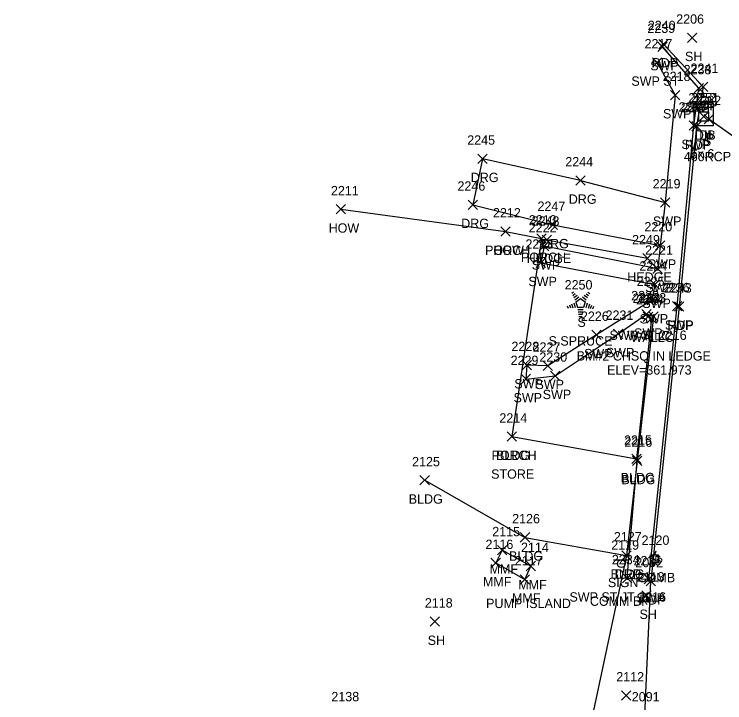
# Model space of a CAD drawing. Extents: x 462930 to 463548, y 29607 to 30453.
# Drawn here: x 463351.85 to 463398.16, y 30246.27 to 30291.16 of the extents above; entities that cross this region are included whole.
import ezdxf

# ---------------------------------------------------------------- set-up
doc = ezdxf.new("R2010")
doc.units = 0
for name, color, linetype in [('D_A', 7, 'Continuous'), ('D_C', 7, 'Continuous'), ('D_I', 7, 'Continuous'), ('D_TIC', 7, 'Continuous'), ('DCP', 7, 'Continuous'), ('DS', 7, 'Continuous'), ('L_A', 7, 'Continuous'), ('L_C', 7, 'Continuous'), ('L_I', 7, 'Continuous'), ('L_TIC', 7, 'Continuous'), ('LAHR', 7, 'Continuous'), ('LBC', 7, 'Continuous'), ('LBF', 7, 'Continuous'), ('LDEFAULT', 7, 'Continuous'), ('LTC', 7, 'Continuous'), ('LW', 7, 'Continuous'), ('P_A', 7, 'Continuous'), ('P_I', 7, 'Continuous'), ('P_TIC', 7, 'Continuous'), ('PET', 7, 'Continuous'), ('R_A', 7, 'Continuous'), ('R_I', 7, 'Continuous'), ('R_TIC', 7, 'Continuous'), ('RDG', 7, 'Continuous'), ('RDP', 7, 'Continuous'), ('RSW', 7, 'Continuous'), ('S_A', 7, 'Continuous'), ('S_C', 7, 'Continuous'), ('S_I', 7, 'Continuous'), ('SSGN', 7, 'Continuous'), ('U_A', 7, 'Continuous'), ('U_I', 7, 'Continuous'), ('UP', 7, 'Continuous')]:
    doc.layers.add(name, color=color, linetype=linetype)

msp = doc.modelspace()

# ---------------------------------------------------------------- linework, layer by layer
at = {"layer": 'D_TIC'}
for points in [[(463396.479, 30284.195), (463397.089, 30284.805)], [(463397.089, 30284.195), (463396.479, 30284.805)], [(463396.809, 30284.016), (463397.419, 30284.626)], [(463397.419, 30284.016), (463396.809, 30284.626)]]:
    msp.add_lwpolyline(points, dxfattribs=at)
at = {"layer": 'DCP'}
msp.add_lwpolyline([(463406.672, 30277.555), (463397.114, 30284.321)], dxfattribs=at)
at = {"layer": 'DS'}
for p, q in [((463396.173, 30285.108), (463397.392, 30285.108)), ((463396.173, 30283.889), (463396.173, 30285.108)), ((463397.392, 30285.108), (463397.392, 30283.889)), ((463396.478, 30284.194), (463396.478, 30284.803)), ((463396.478, 30284.803), (463397.087, 30284.803)), ((463396.784, 30284.499), (463396.784, 30284.499)), ((463396.784, 30284.499), (463396.784, 30284.499)), ((463397.087, 30284.803), (463397.087, 30284.194)), ((463397.087, 30284.194), (463396.478, 30284.194)), ((463397.392, 30283.889), (463396.173, 30283.889))]:
    msp.add_line(p, q, dxfattribs=at)
at = {"layer": 'L_TIC'}
for points in [[(463395.721, 30289.323), (463396.331, 30289.933)], [(463396.331, 30289.323), (463395.721, 30289.933)], [(463372.834, 30278.135), (463373.444, 30278.745)], [(463373.444, 30278.135), (463372.834, 30278.745)], [(463383.565, 30276.688), (463384.175, 30277.298)], [(463384.175, 30276.688), (463383.565, 30277.298)], [(463383.565, 30276.688), (463384.175, 30277.298)], [(463384.175, 30276.688), (463383.565, 30277.298)], [(463385.902, 30276.227), (463386.512, 30276.837)], [(463386.512, 30276.227), (463385.902, 30276.837)], [(463386.258, 30276.152), (463386.868, 30276.762)], [(463386.868, 30276.152), (463386.258, 30276.762)], [(463392.808, 30274.939), (463393.418, 30275.549)], [(463393.418, 30274.939), (463392.808, 30275.549)], [(463392.85, 30271.115), (463393.46, 30271.725)], [(463393.46, 30271.115), (463392.85, 30271.725)], [(463393.079, 30271.016), (463393.689, 30271.626)], [(463393.689, 30271.016), (463393.079, 30271.626)], [(463383.985, 30263.314), (463384.595, 30263.924)], [(463384.595, 30263.314), (463383.985, 30263.924)], [(463383.985, 30263.314), (463384.595, 30263.924)], [(463384.595, 30263.314), (463383.985, 30263.924)], [(463392.107, 30261.866), (463392.717, 30262.476)], [(463392.717, 30261.866), (463392.107, 30262.476)], [(463392.153, 30261.737), (463392.763, 30262.347)], [(463392.763, 30261.737), (463392.153, 30262.347)], [(463378.295, 30260.466), (463378.905, 30261.076)], [(463378.905, 30260.466), (463378.295, 30261.076)], [(463384.833, 30256.748), (463385.443, 30257.358)], [(463385.443, 30256.748), (463384.833, 30257.358)], [(463383.348, 30255.906), (463383.958, 30256.516)], [(463383.958, 30255.906), (463383.348, 30256.516)], [(463391.445, 30255.571), (463392.055, 30256.181)], [(463392.055, 30255.571), (463391.445, 30256.181)], [(463382.922, 30255.075), (463383.532, 30255.685)], [(463383.532, 30255.075), (463382.922, 30255.685)], [(463385.221, 30254.879), (463385.831, 30255.489)], [(463385.831, 30254.879), (463385.221, 30255.489)], [(463384.814, 30254.004), (463385.424, 30254.614)], [(463385.424, 30254.004), (463384.814, 30254.614)], [(463392.758, 30252.952), (463393.368, 30253.562)], [(463393.368, 30252.952), (463392.758, 30253.562)], [(463378.954, 30251.255), (463379.564, 30251.865)], [(463379.564, 30251.255), (463378.954, 30251.865)], [(463391.428, 30246.438), (463392.038, 30247.048)], [(463392.038, 30246.438), (463391.428, 30247.048)]]:
    msp.add_lwpolyline(points, dxfattribs=at)
at = {"layer": 'LAHR'}
msp.add_lwpolyline([(463386.563, 30276.457), (463393.113, 30275.244)], dxfattribs=at)
at = {"layer": 'LBC'}
for points in [[(463373.139, 30278.44), (463383.87, 30276.993)], [(463384.29, 30263.619), (463392.412, 30262.171), (463392.458, 30262.042)], [(463392.458, 30262.042), (463391.75, 30255.876)], [(463378.6, 30260.771), (463385.138, 30257.053), (463391.75, 30255.876)]]:
    msp.add_lwpolyline(points, dxfattribs=at)
at = {"layer": 'LBF'}
msp.add_lwpolyline([(463383.87, 30276.993), (463386.207, 30276.532), (463384.29, 30263.619)], dxfattribs=at)
at = {"layer": 'LDEFAULT'}
for points in [[(463385.526, 30255.184), (463383.653, 30256.211), (463383.227, 30255.38), (463385.119, 30254.309)], [(463385.119, 30254.309), (463385.526, 30255.184)]]:
    msp.add_lwpolyline(points, dxfattribs=at)
at = {"layer": 'LTC'}
for p, q in [((463388.192, 30272.972), (463388.3, 30273.051)), ((463388.256, 30272.83), (463388.417, 30272.947)), ((463388.32, 30272.688), (463388.534, 30272.844)), ((463389.002, 30272.833), (463389.209, 30272.682)), ((463389.115, 30272.939), (463389.282, 30272.817)), ((463389.228, 30273.045), (463389.355, 30272.952)), ((463388.384, 30272.546), (463388.651, 30272.741)), ((463388.452, 30272.408), (463388.76, 30272.631)), ((463388.452, 30272.408), (463388.57, 30272.044)), ((463388.76, 30272.631), (463389.064, 30272.41)), ((463388.888, 30272.727), (463389.135, 30272.547)), ((463389.064, 30272.41), (463388.945, 30272.044)), ((463387.897, 30272.143), (463387.943, 30272)), ((463388.036, 30272.209), (463388.1, 30272.01)), ((463388.175, 30272.275), (463388.257, 30272.02)), ((463388.313, 30272.341), (463388.414, 30272.03)), ((463388.945, 30272.044), (463388.57, 30272.044)), ((463388.933, 30271.891), (463388.584, 30271.891)), ((463389.198, 30272.328), (463389.095, 30272.011)), ((463389.333, 30272.252), (463389.245, 30271.982)), ((463389.469, 30272.175), (463389.396, 30271.953)), ((463389.604, 30272.099), (463389.547, 30271.924)), ((463388.908, 30271.739), (463388.607, 30271.739)), ((463388.882, 30271.587), (463388.629, 30271.587)), ((463388.857, 30271.434), (463388.651, 30271.434))]:
    msp.add_line(p, q, dxfattribs=at)
at = {"layer": 'LW'}
for points in [[(463393.384, 30271.321), (463392.412, 30262.171)], [(463393.155, 30271.42), (463393.384, 30271.321)]]:
    msp.add_lwpolyline(points, dxfattribs=at)
at = {"layer": 'P_TIC'}
for points in [[(463393.855, 30288.906), (463394.465, 30289.516)], [(463394.465, 30288.906), (463393.855, 30289.516)], [(463396.441, 30286.118), (463397.051, 30286.728)], [(463397.051, 30286.118), (463396.441, 30286.728)], [(463396.017, 30283.551), (463396.627, 30284.161)], [(463396.627, 30283.551), (463396.017, 30284.161)], [(463394.878, 30271.79), (463395.488, 30272.4)], [(463395.488, 30271.79), (463394.878, 30272.4)], [(463393.041, 30253.888), (463393.651, 30254.498)], [(463393.651, 30253.888), (463393.041, 30254.498)]]:
    msp.add_lwpolyline(points, dxfattribs=at)
at = {"layer": 'PET'}
for points in [[(463394.16, 30289.211), (463396.746, 30286.423), (463396.322, 30283.856), (463395.183, 30272.095)], [(463395.183, 30272.095), (463393.346, 30254.193)], [(463351.849, 30230.001), (463360.302, 30224.79), (463363.81, 30222.829), (463366.719, 30221.627), (463371.212, 30221.775), (463377.641, 30225.283), (463383.918, 30231.013), (463388.099, 30237.45), (463392.941, 30245.442), (463393.346, 30254.193)]]:
    msp.add_lwpolyline(points, dxfattribs=at)
at = {"layer": 'R_TIC'}
for points in [[(463393.804, 30288.722), (463394.414, 30289.332)], [(463394.414, 30288.722), (463393.804, 30289.332)], [(463393.444, 30287.714), (463394.054, 30288.324)], [(463394.054, 30287.714), (463393.444, 30288.324)], [(463396.163, 30286.025), (463396.773, 30286.635)], [(463396.773, 30286.025), (463396.163, 30286.635)], [(463394.629, 30285.586), (463395.239, 30286.196)], [(463395.239, 30285.586), (463394.629, 30286.196)], [(463395.832, 30283.591), (463396.442, 30284.201)], [(463396.442, 30283.591), (463395.832, 30284.201)], [(463382.063, 30281.434), (463382.673, 30282.044)], [(463382.673, 30281.434), (463382.063, 30282.044)], [(463388.452, 30280.018), (463389.062, 30280.628)], [(463389.062, 30280.018), (463388.452, 30280.628)], [(463381.442, 30278.436), (463382.052, 30279.046)], [(463382.052, 30278.436), (463381.442, 30279.046)], [(463393.976, 30278.583), (463394.586, 30279.193)], [(463394.586, 30278.583), (463393.976, 30279.193)], [(463386.643, 30277.118), (463387.253, 30277.728)], [(463387.253, 30277.118), (463386.643, 30277.728)], [(463386.072, 30275.73), (463386.682, 30276.34)], [(463386.682, 30275.73), (463386.072, 30276.34)], [(463393.634, 30275.784), (463394.244, 30276.394)], [(463394.244, 30275.784), (463393.634, 30276.394)], [(463385.857, 30274.65), (463386.467, 30275.26)], [(463386.467, 30274.65), (463385.857, 30275.26)], [(463393.48, 30274.261), (463394.09, 30274.871)], [(463394.09, 30274.261), (463393.48, 30274.871)], [(463393.285, 30273.228), (463393.895, 30273.838)], [(463393.895, 30273.228), (463393.285, 30273.838)], [(463393.105, 30272.218), (463393.715, 30272.828)], [(463393.715, 30272.218), (463393.105, 30272.828)], [(463394.756, 30271.816), (463395.366, 30272.426)], [(463395.366, 30271.816), (463394.756, 30272.426)], [(463392.748, 30271.289), (463393.358, 30271.899)], [(463393.358, 30271.289), (463392.748, 30271.899)], [(463393.211, 30271.147), (463393.821, 30271.757)], [(463393.821, 30271.147), (463393.211, 30271.757)], [(463389.488, 30269.946), (463390.098, 30270.556)], [(463390.098, 30269.946), (463389.488, 30270.556)], [(463390.904, 30270.015), (463391.514, 30270.625)], [(463391.514, 30270.015), (463390.904, 30270.625)], [(463384.943, 30267.978), (463385.553, 30268.588)], [(463385.553, 30267.978), (463384.943, 30268.588)], [(463386.319, 30267.938), (463386.929, 30268.548)], [(463386.929, 30267.938), (463386.319, 30268.548)], [(463386.79, 30267.286), (463387.4, 30267.896)], [(463387.4, 30267.286), (463386.79, 30267.896)], [(463384.891, 30267.071), (463385.501, 30267.681)], [(463385.501, 30267.071), (463384.891, 30267.681)], [(463391.445, 30255.571), (463392.055, 30256.181)], [(463392.055, 30255.571), (463391.445, 30256.181)], [(463391.487, 30254.08), (463392.097, 30254.69)], [(463392.097, 30254.08), (463391.487, 30254.69)], [(463392.903, 30254.011), (463393.513, 30254.621)], [(463393.513, 30254.011), (463392.903, 30254.621)]]:
    msp.add_lwpolyline(points, dxfattribs=at)
at = {"layer": 'RDG'}
for points in [[(463388.757, 30280.323), (463382.368, 30281.739), (463381.747, 30278.741), (463386.948, 30277.423)], [(463388.757, 30280.323), (463394.281, 30278.888)], [(463386.948, 30277.423), (463393.939, 30276.089)]]:
    msp.add_lwpolyline(points, dxfattribs=at)
at = {"layer": 'RDP'}
msp.add_lwpolyline([(463391.75, 30255.876), (463387.853, 30237.498), (463385.416, 30235.81), (463378.004, 30240.013), (463371.934, 30243.569)], dxfattribs=at)
at = {"layer": 'RSW'}
for points in [[(463391.792, 30254.385), (463393.208, 30254.316), (463395.061, 30272.121), (463396.137, 30283.896), (463396.468, 30286.33), (463394.109, 30289.027)], [(463393.749, 30288.019), (463394.934, 30285.891), (463394.281, 30278.888), (463393.939, 30276.089), (463393.785, 30274.566), (463386.377, 30276.035), (463386.162, 30274.955), (463393.59, 30273.533), (463393.41, 30272.523), (463389.793, 30270.251), (463386.624, 30268.243), (463385.248, 30268.283), (463385.196, 30267.376), (463387.095, 30267.591), (463391.209, 30270.32), (463393.053, 30271.594), (463393.516, 30271.452)], [(463393.516, 30271.452), (463392.458, 30262.042)], [(463391.792, 30254.385), (463392.458, 30262.042)]]:
    msp.add_lwpolyline(points, dxfattribs=at)
at = {"layer": 'SSGN'}
for p, q in [((463390.913, 30255.59), (463391.929, 30255.59)), ((463391.415, 30255.336), (463391.415, 30255.336))]:
    msp.add_line(p, q, dxfattribs=at)
msp.add_circle((463391.415, 30255.336), 0.254, dxfattribs=at)
at = {"layer": 'UP'}
for p, q in [((463393.658, 30256.157), (463393.582, 30255.903)), ((463393.328, 30255.395), (463393.328, 30255.903)), ((463393.328, 30255.903), (463393.836, 30255.903)), ((463393.836, 30255.903), (463393.836, 30255.395)), ((463393.836, 30255.395), (463393.328, 30255.395)), ((463393.506, 30255.141), (463393.582, 30255.395)), ((463393.582, 30255.649), (463393.582, 30255.649))]:
    msp.add_line(p, q, dxfattribs=at)
msp.add_circle((463393.582, 30255.649), 0.254, dxfattribs=at)

# ---------------------------------------------------------------- texts
at = {"layer": 'D_A'}
for s, height, p in [('DIB', 0.6096, (463396.206, 30282.976)), ('DI', 0.6096, (463396.496, 30282.975)), ('P', 0.61, (463396.924, 30282.797))]:
    msp.add_text(s, height=height, dxfattribs=at).set_placement(p)
at = {"layer": 'D_C'}
for s, p in [('460RCP', (463395.489, 30281.578)), ('.6x.6', (463395.706, 30281.756))]:
    msp.add_text(s, height=0.6096, dxfattribs=at).set_placement(p)
at = {"layer": 'D_I'}
for s, p in [('2252', (463395.79, 30285.414)), ('2251', (463395.963, 30285.413)), ('2262', (463396.106, 30285.235))]:
    msp.add_text(s, height=0.6096, dxfattribs=at).set_placement(p)
at = {"layer": 'L_A'}
for s, height, p in [('SH', 0.6096, (463395.565, 30288.104)), ('HOW', 0.6096, (463372.342, 30276.916)), ('PORCH', 0.6096, (463382.536, 30275.469)), ('HOW', 0.6096, (463383.073, 30275.469)), ('PORCH', 0.6096, (463384.873, 30275.008)), ('HEDGE', 0.6096, (463385.253, 30274.933)), ('HEDGE', 0.6096, (463391.803, 30273.72)), ('S', 0.61, (463388.555, 30270.775)), ('WALLC', 0.6096, (463391.794, 30269.896)), ('WALLC', 0.6096, (463392.023, 30269.797)), ('PORCH', 0.6096, (463382.956, 30262.095)), ('BLDG', 0.6096, (463383.251, 30262.095)), ('BLDG', 0.6096, (463391.373, 30260.647)), ('BLDG', 0.6096, (463391.419, 30260.518)), ('BLDG', 0.6096, (463377.561, 30259.247)), ('BLDG', 0.6096, (463384.099, 30255.529)), ('MMF', 0.6096, (463382.825, 30254.687)), ('BLDG', 0.6096, (463390.711, 30254.352)), ('MMF', 0.6096, (463382.399, 30253.856)), ('MMF', 0.6096, (463384.698, 30253.66)), ('MMF', 0.6096, (463384.291, 30252.785)), ('SH', 0.6096, (463392.602, 30251.733)), ('SH', 0.6096, (463378.798, 30250.036))]:
    msp.add_text(s, height=height, dxfattribs=at).set_placement(p)
at = {"layer": 'L_C'}
for s, p in [('S.SPRUCE', (463386.673, 30269.556)), ('BM#2 CHSQ IN LEDGE', (463388.507, 30268.578)), ('ELEV=361.973', (463390.485, 30267.663)), ('STORE', (463382.932, 30260.876)), ('PUMP ISLAND', (463382.605, 30252.441))]:
    msp.add_text(s, height=0.6096, dxfattribs=at).set_placement(p)
at = {"layer": 'L_I'}
for s, p in [('2206', (463394.992, 30290.542)), ('2211', (463372.491, 30279.354)), ('2212', (463383.049, 30277.907)), ('2212', (463383.049, 30277.907)), ('2213', (463385.386, 30277.446)), ('2248', (463385.569, 30277.371)), ('2249', (463392.117, 30276.158)), ('2250', (463387.722, 30273.213)), ('2263', (463392.147, 30272.334)), ('2264', (463392.376, 30272.235)), ('2214', (463383.469, 30264.533)), ('2214', (463383.469, 30264.533)), ('2215', (463391.591, 30263.085)), ('2216', (463391.62, 30262.956)), ('2125', (463377.779, 30261.685)), ('2126', (463384.3, 30257.967)), ('2115', (463383.005, 30257.125)), ('2127', (463390.929, 30256.79)), ('2116', (463382.562, 30256.294)), ('2114', (463384.878, 30256.098)), ('2117', (463384.471, 30255.223)), ('2113', (463392.415, 30254.171)), ('2118', (463378.611, 30252.474)), ('2112', (463391.085, 30247.657)), ('2138', (463372.518, 30246.364))]:
    msp.add_text(s, height=0.6096, dxfattribs=at).set_placement(p)
at = {"layer": 'LTC'}
msp.add_text('.', height=0.316, rotation=270, dxfattribs=at).set_placement((463388.725, 30272.331))
at = {"layer": 'P_A'}
for p in [(463393.394, 30287.687), (463395.98, 30284.899), (463395.556, 30282.332), (463394.417, 30270.571), (463392.58, 30252.669)]:
    msp.add_text('RDP', height=0.6096, dxfattribs=at).set_placement(p)
at = {"layer": 'P_I'}
for s, p in [('2240', (463393.14, 30290.125)), ('2241', (463395.925, 30287.337)), ('2242', (463395.328, 30284.77)), ('2243', (463394.189, 30273.009)), ('2092', (463392.328, 30255.107)), ('2091', (463392.096, 30246.356))]:
    msp.add_text(s, height=0.6096, dxfattribs=at).set_placement(p)
at = {"layer": 'R_A'}
for s, p in [('SWP', (463393.305, 30287.503)), ('SWP ST', (463392.071, 30286.495)), ('SWP', (463395.664, 30284.806)), ('SWP', (463394.13, 30284.367)), ('SWP', (463395.333, 30282.372)), ('DRG', (463381.602, 30280.215)), ('DRG', (463387.991, 30278.799)), ('SWP', (463393.477, 30277.364)), ('DRG', (463380.981, 30277.217)), ('DRG', (463386.182, 30275.899)), ('SWP', (463393.135, 30274.565)), ('SWP', (463385.573, 30274.511)), ('SWP', (463385.358, 30273.431)), ('SWP', (463392.981, 30273.042)), ('SWP', (463392.786, 30272.009)), ('SWP', (463392.606, 30270.999)), ('SWP', (463394.257, 30270.597)), ('SWP JT 2216', (463390.643, 30269.928)), ('SWP', (463392.249, 30270.07)), ('SWP', (463388.989, 30268.727)), ('SWP', (463390.405, 30268.796)), ('SWP', (463384.444, 30266.759)), ('SWP', (463385.82, 30266.719)), ('SWP', (463384.392, 30265.852)), ('SWP', (463386.291, 30266.067)), ('DRP', (463390.984, 30254.352)), ('SWP ST JT 2216', (463388.036, 30252.861)), ('SWP', (463392.404, 30252.792))]:
    msp.add_text(s, height=0.6096, dxfattribs=at).set_placement(p)
at = {"layer": 'R_I'}
for s, p in [('2239', (463393.113, 30289.941)), ('2217', (463392.928, 30288.933)), ('2238', (463395.474, 30287.244)), ('2218', (463394.113, 30286.805)), ('2237', (463395.143, 30284.81)), ('2245', (463381.374, 30282.653)), ('2244', (463387.763, 30281.237)), ('2246', (463380.737, 30279.655)), ('2219', (463393.458, 30279.802)), ('2247', (463385.954, 30278.337)), ('2222', (463385.383, 30276.949)), ('2220', (463392.919, 30277.003)), ('2223', (463385.168, 30275.869)), ('2221', (463392.964, 30275.48)), ('2224', (463392.596, 30274.447)), ('2225', (463392.416, 30273.437)), ('2236', (463394.051, 30273.035)), ('2232', (463392.059, 30272.508)), ('2233', (463392.522, 30272.366)), ('2226', (463388.783, 30271.165)), ('2231', (463390.388, 30271.234)), ('2228', (463384.254, 30269.197)), ('2227', (463385.63, 30269.157)), ('2230', (463386.075, 30268.505)), ('2229', (463384.2, 30268.29)), ('2127', (463390.929, 30256.79)), ('2234', (463390.798, 30255.299)), ('2235', (463392.214, 30255.23))]:
    msp.add_text(s, height=0.6096, dxfattribs=at).set_placement(p)
at = {"layer": 'S_A'}
msp.add_text('SIGN', height=0.6096, dxfattribs=at).set_placement((463390.543, 30253.806))
at = {"layer": 'S_C'}
msp.add_text('COMM BP', height=0.6096, dxfattribs=at).set_placement((463389.367, 30252.587))
at = {"layer": 'S_I'}
msp.add_text('2119', height=0.6096, dxfattribs=at).set_placement((463390.759, 30256.244))
at = {"layer": 'U_A'}
msp.add_text('COMB', height=0.6096, dxfattribs=at).set_placement((463392.48, 30254.125))
at = {"layer": 'U_I'}
msp.add_text('2120', height=0.6096, dxfattribs=at).set_placement((463392.735, 30256.563))

doc.saveas('drawing.dxf')
